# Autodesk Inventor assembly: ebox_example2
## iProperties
Shininess: 3
Length Units: 11272
Angle Units: 11279
Time Units: 11290
Mass Units: 11286
Length Display Precision: 3
Angle Display Precision: 2
Compacted: True
Created: 2001-07
Part Number: ebox_example2
Document SubType Name: Assembly
Designer: Autodesk, Inc.
Project: Inventor Samples
Mass: 3231.29 g
Surface Area: 3188.73 cm^2
Volume: 412.709 cm^3
Density: 7.82946 g/cm^3
Density: 0.0
Volumn: 0.0
Area: 0.0
PropertySet Name: Model Information
Control State: 0
Master: False
Checked Out: False
Author: Autodesk, Inc.
Revision Number: A
Title: Metal Container
